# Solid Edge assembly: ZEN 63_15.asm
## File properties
Title: Zylinder
Author: ahadarics
Template: iso metric assembly.asm
Last saved by: ahadarics
Revision: 7
Application: Solid Edge
Username: ahadarics
Dokumentum tartalom típus: 1
Document Number: ZEN 63/15
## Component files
Kit_2.par
Kit_1.par
Kolbenstange.par
Profilrohr.par
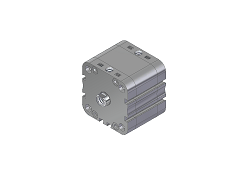
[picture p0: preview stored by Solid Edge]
